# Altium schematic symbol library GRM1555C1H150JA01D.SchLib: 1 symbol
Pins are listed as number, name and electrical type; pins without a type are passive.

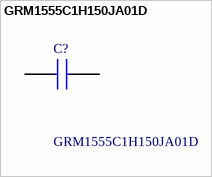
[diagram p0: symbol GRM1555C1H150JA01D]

## GRM1555C1H150JA01D
designator C?
Ceramic Capacitors MLCC 0402 15pF 50V Murata 0402 GRM 15pF Ceramic Multilayer Capacitor, 50 V dc C0G Dielectric +/-5% SMD; Manufacturer_Name: Murata Electronics; Geometry.Height: 0.7mm
footprint CAPC1005X70N
pins: 1, 2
